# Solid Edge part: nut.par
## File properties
Author: Deepak Maini
Template: normal.par
Last saved by: Robert a Rhodes jr
Revision: 3
Application: Solid Edge
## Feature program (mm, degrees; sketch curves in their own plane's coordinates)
sketch for "unnamed Protrusion 1" plane through (0, 0, 0) normal (0, 0, 1) x-axis (1, 0, 0)
  line (-10, 0) -> (-5.1679, 8.5611)
  line (-5.1679, 8.5611) -> (5.1679, 8.5611)
  line (5.1679, 8.5611) -> (10, 0)
  line (10, 0) -> (5.1679, -8.5611)
  line (5.1679, -8.5611) -> (-4.8321, -8.5611)
  line (-4.8321, -8.5611) -> (-10, 0)
  dimension (linear) = 10
extrude "unnamed Protrusion 1" add finite 10 along -normal
sketch for "unnamed Hole 1" plane through (0, 0, 0) normal (0, 0, 1) x-axis (1, 0, 0)
  hole centre (0, 0) bore radius 5
hole "unnamed Hole 1" through
sketch for "unnamed RevolvedCutout 1" plane through (0, 0, 0) normal (0, -1, 0) x-axis (1, 0, 0)
  arc centre (8, -2) radius 2 from (8, 0) to (10, -2) cw
  line (10.5093, -2) -> (10, -2)
  line (10.5093, 2.8678) -> (10.5093, -2)
  line (8, 2.8678) -> (10.5093, 2.8678)
  line (8, 0) -> (8, 2.8678)
revolve "unnamed RevolvedCutout 1" cut finite 360 deg
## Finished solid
Body 1: solid body, 10 faces, 21 edges, 12 vertices.
  Faces by surface: plane 8, cylinder 1, torus 1
  Edges by curve: line 12, intersection 6, circle 3
Bounding box of the edges (mm; curved faces can reach further): 20.000 x 17.122 x 10.000, from (-10, -8.5611, -10) to (10, 8.5611, 0).
Cylindrical faces by radius (mm): R5 x1
Toroidal faces (ring radius, tube radius in mm): R8 r2 x1
Planar faces by outward normal: +y 1, +z 1, -y 1, -z 1, oblique 4
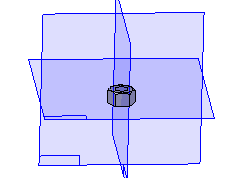
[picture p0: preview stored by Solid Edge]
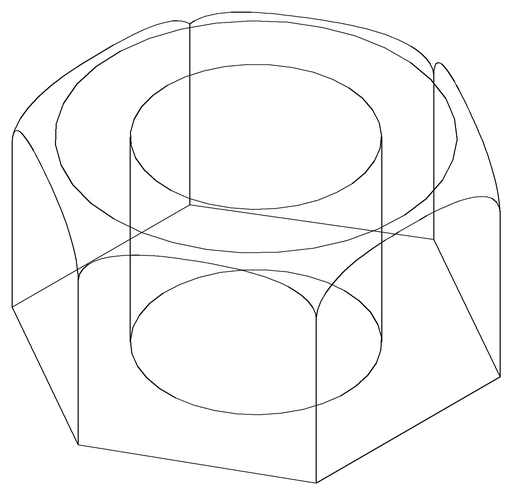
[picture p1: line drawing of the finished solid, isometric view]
